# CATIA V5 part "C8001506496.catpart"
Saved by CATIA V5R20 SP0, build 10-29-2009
Part number: C8001506496
Source: Unknown
Property "A": "70"
Property "ARTICLENO": "C8001506496"
Property "B": "32"
Property "BOMINFO": "C8001506496"
Property "C": "120"
Property "CA": "C8001506496"
Property "D1": "120"
Property "DES": "ROTATING EYEBOLT WITH RING Ton 15 M64x96"
Property "E": "130"
Property "H": "280"
Property "L": "96"
Property "LINA": "C8001506496"
Property "NB": "C8001506496"
Property "NBSYN": "$CODE."
Property "NN": "C800"
Property "NT": "Rotating eyebolt with ring"
Property "SIZE": "M64"
Property "SUPPLIER": "CF"
Property "SW": "95"
Property "WEIGHT": "10000"
Property "WLL": "15.00"
Bounding box of the stored display mesh (mm): x -67 to 67, y -96 to 311.813, z -60 to 60
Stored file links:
  C:\Users\Utente\Desktop\3D files 800\C8001506496.catpart
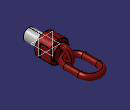
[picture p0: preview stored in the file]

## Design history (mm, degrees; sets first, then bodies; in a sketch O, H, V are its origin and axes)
Body1 "Geometry.1" (main body)
  Solid1 "C8001506496.catpart": solid without history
